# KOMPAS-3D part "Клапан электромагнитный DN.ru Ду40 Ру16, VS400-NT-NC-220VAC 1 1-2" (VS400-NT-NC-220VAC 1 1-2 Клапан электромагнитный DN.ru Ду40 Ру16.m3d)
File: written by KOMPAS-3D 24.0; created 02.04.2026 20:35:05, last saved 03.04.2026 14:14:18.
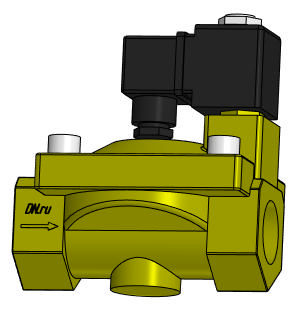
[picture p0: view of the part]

Document properties: Автор: artio; Полное имя файла: C:\Users\artio\OneDrive\Рабочий стол\Клапан электромагнитный DN.ru VS4x-xT-NC-x\VS400-NT-NC\VS400-NT-NC-220VAC 1 1-2 Клапан электромагнитный DN.ru Ду40 Ру16.m3d

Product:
- Body: Тело 1  | qty 1
    Масса: 4.144257
- Part/product: Клапан электромагнитный DN.ru Ду40 Ру16  | designation VS400-NT-NC-220VAC 1 1-2
    Масса: 2.321
    Раздел спецификации: Прочие изделия
    Примечание: D130-04665
    additional columns: ef56311e-7521-43dc-8291-0e6108b3d81d; VS400-ET-NC-220VAC 1 1-2; artio; c; Шероховатость не задана; Да

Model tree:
1. Операция без истории:1

Expressions: VS400-NT-NC-220VAC 1 1-2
